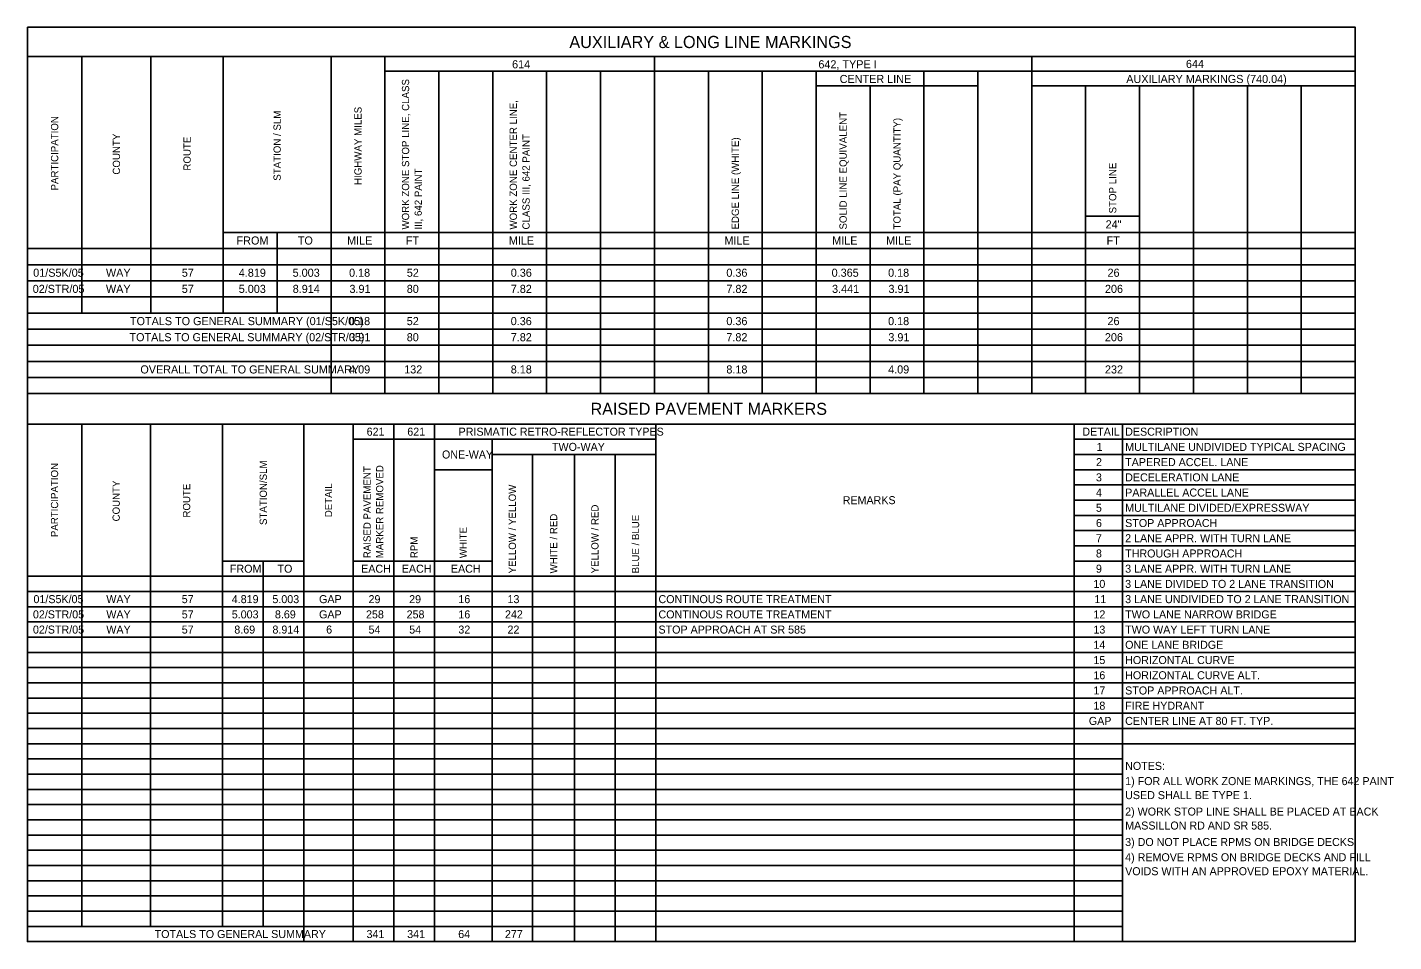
# Model space of a CAD drawing. Extents: x 169.3 to 200.7, y -37 to -16.
import ezdxf

# ---------------------------------------------------------------- set-up
doc = ezdxf.new("R2010")
doc.units = 0
doc.layers.add('SC_Scratch1', color=7, linetype='Continuous')
doc.layers.add('SH_Text', color=7, linetype='Continuous')

msp = doc.modelspace()

# ---------------------------------------------------------------- linework, layer by layer
at = {"layer": 'SC_Scratch1'}
msp.add_lwpolyline([(169.301, -15.985), (199.801, -15.985), (199.801, -36.985), (169.301, -36.985)], close=True, dxfattribs=at)
at = {"layer": 'SH_Text'}
for p, q in [((169.301, -15.985), (199.801, -15.985)), ((169.301, -15.985), (169.301, -24.398)), ((199.801, -15.985), (199.801, -24.398)), ((169.301, -16.658), (199.801, -16.658)), ((170.554, -16.658), (170.554, -22.547)), ((172.139, -16.658), (172.139, -22.547)), ((173.8, -16.658), (173.8, -22.547)), ((176.277, -16.658), (176.277, -24.398)), ((177.515, -16.658), (177.515, -24.398)), ((183.705, -16.658), (183.705, -24.398)), ((192.372, -16.658), (192.372, -24.398)), ((177.515, -16.995), (199.801, -16.995)), ((178.753, -16.995), (178.753, -24.398)), ((179.991, -16.995), (179.991, -24.398)), ((181.229, -16.995), (181.229, -24.398)), ((182.467, -16.995), (182.467, -24.398)), ((184.943, -16.995), (184.943, -24.398)), ((186.182, -16.995), (186.182, -24.398)), ((187.42, -16.995), (187.42, -24.398)), ((189.896, -16.995), (189.896, -24.398)), ((191.134, -16.995), (191.134, -24.398)), ((187.42, -17.331), (191.134, -17.331)), ((188.658, -17.331), (188.658, -24.398)), ((192.372, -17.331), (199.801, -17.331)), ((193.61, -17.331), (193.61, -24.398)), ((194.848, -17.331), (194.848, -24.398)), ((196.086, -17.331), (196.086, -24.398)), ((197.325, -17.331), (197.325, -24.398)), ((198.563, -17.331), (198.563, -24.398)), ((193.61, -20.326), (194.848, -20.326)), ((173.8, -20.696), (199.801, -20.696)), ((175.038, -20.696), (175.038, -22.547)), ((169.301, -21.066), (199.801, -21.066)), ((169.301, -21.437), (199.801, -21.437)), ((169.301, -21.807), (199.801, -21.807)), ((169.301, -22.177), (199.801, -22.177)), ((169.301, -22.547), (199.801, -22.547)), ((169.301, -22.917), (199.801, -22.917)), ((169.301, -23.287), (199.801, -23.287)), ((169.301, -23.658), (199.801, -23.658)), ((169.301, -24.028), (199.801, -24.028)), ((169.301, -24.398), (199.801, -24.398)), ((169.301, -24.398), (169.301, -36.985)), ((169.301, -24.398), (199.801, -24.398)), ((199.801, -24.398), (199.801, -36.985)), ((169.301, -25.097), (199.801, -25.097)), ((170.55, -25.097), (170.55, -36.635)), ((172.131, -25.097), (172.131, -36.635)), ((173.787, -25.097), (173.787, -36.635)), ((175.654, -25.097), (175.654, -36.985)), ((176.783, -25.097), (176.783, -36.985)), ((177.716, -25.097), (177.716, -36.985)), ((178.65, -25.097), (178.65, -36.985)), ((183.738, -25.097), (183.738, -36.985)), ((193.343, -25.097), (193.343, -36.985)), ((194.457, -25.097), (194.457, -36.985)), ((176.783, -25.447), (183.738, -25.447)), ((179.974, -25.447), (179.974, -36.985)), ((193.343, -25.447), (199.801, -25.447)), ((179.974, -25.796), (183.738, -25.796)), ((180.908, -25.796), (180.908, -36.985)), ((181.871, -25.796), (181.871, -36.985)), ((182.805, -25.796), (182.805, -36.985)), ((193.343, -25.796), (199.801, -25.796)), ((178.65, -26.146), (179.974, -26.146)), ((193.343, -26.146), (199.801, -26.146)), ((193.343, -26.496), (199.801, -26.496)), ((193.343, -26.845), (199.801, -26.845)), ((193.343, -27.195), (199.801, -27.195)), ((193.343, -27.545), (199.801, -27.545)), ((193.343, -27.894), (199.801, -27.894)), ((173.787, -28.244), (175.654, -28.244)), ((174.72, -28.244), (174.72, -36.635)), ((176.783, -28.244), (179.974, -28.244)), ((193.343, -28.244), (199.801, -28.244)), ((169.301, -28.594), (199.801, -28.594)), ((169.301, -28.943), (199.801, -28.943)), ((169.301, -29.293), (199.801, -29.293)), ((169.301, -29.643), (199.801, -29.643)), ((169.301, -29.992), (199.801, -29.992)), ((169.301, -30.342), (199.801, -30.342)), ((169.301, -30.691), (199.801, -30.691)), ((169.301, -31.041), (199.801, -31.041)), ((169.301, -31.391), (199.801, -31.391)), ((169.301, -31.74), (199.801, -31.74)), ((169.301, -32.09), (199.801, -32.09)), ((169.301, -32.44), (199.801, -32.44)), ((169.301, -32.789), (194.457, -32.789)), ((169.301, -33.139), (194.457, -33.139)), ((169.301, -33.489), (194.457, -33.489)), ((169.301, -33.838), (194.457, -33.838)), ((169.301, -34.188), (194.457, -34.188)), ((169.301, -34.538), (194.457, -34.538)), ((169.301, -34.887), (194.457, -34.887)), ((169.301, -35.237), (194.457, -35.237)), ((169.301, -35.587), (194.457, -35.587)), ((169.301, -35.936), (194.457, -35.936)), ((169.301, -36.286), (194.457, -36.286)), ((169.301, -36.635), (194.457, -36.635)), ((169.301, -36.985), (199.801, -36.985))]:
    msp.add_line(p, q, dxfattribs=at)

# ---------------------------------------------------------------- texts
for s, height, p in [('AUXILIARY & LONG LINE MARKINGS', 0.27863, (181.751, -16.461)), ('614', 0.1858, (180.436, -16.927)), ('642, TYPE I', 0.18575, (187.471, -16.927)), ('644', 0.1858, (195.913, -16.919)), ('CENTER LINE', 0.18575, (187.96, -17.264)), ('AUXILIARY MARKINGS (740.04)', 0.18575, (194.543, -17.264)), ('24"', 0.1858, (194.068, -20.604)), ('FROM', 0.1858, (174.107, -20.974)), ('TO', 0.1858, (175.514, -20.974)), ('MILE', 0.1858, (176.646, -20.974)), ('FT', 0.1858, (177.995, -20.974)), ('MILE', 0.1858, (180.361, -20.974)), ('MILE', 0.1858, (185.313, -20.974)), ('MILE', 0.1858, (187.789, -20.974)), ('MILE', 0.1858, (189.027, -20.974)), ('FT', 0.1858, (194.091, -20.974)), ('01/S5K/05', 0.1858, (169.436, -21.714)), ('WAY', 0.1858, (171.107, -21.714)), ('57', 0.1858, (172.849, -21.714)), ('4.819', 0.1858, (174.158, -21.714)), ('5.003', 0.1858, (175.395, -21.714)), ('0.18', 0.1858, (176.691, -21.714)), ('52', 0.1858, (178.017, -21.714)), ('0.36', 0.1858, (180.405, -21.714)), ('0.36', 0.1858, (185.357, -21.714)), ('0.365', 0.1858, (187.775, -21.714)), ('0.18', 0.1858, (189.072, -21.714)), ('26', 0.1858, (194.112, -21.714)), ('02/STR/05', 0.1858, (169.425, -22.085)), ('WAY', 0.1858, (171.107, -22.085)), ('57', 0.1858, (172.849, -22.085)), ('5.003', 0.1858, (174.157, -22.085)), ('8.914', 0.1858, (175.397, -22.085)), ('3.91', 0.1858, (176.7, -22.085)), ('80', 0.1858, (178.016, -22.085)), ('7.82', 0.1858, (180.405, -22.085)), ('7.82', 0.1858, (185.358, -22.085)), ('3.441', 0.1858, (187.785, -22.085)), ('3.91', 0.1858, (189.081, -22.085)), ('206', 0.1858, (194.053, -22.085)), ('TOTALS TO GENERAL SUMMARY (01/S5K/05)', 0.18575, (171.659, -22.825)), ('0.18', 0.1858, (176.691, -22.825)), ('52', 0.1858, (178.016, -22.825)), ('0.36', 0.1858, (180.404, -22.825)), ('0.36', 0.1858, (185.357, -22.825)), ('0.18', 0.1858, (189.072, -22.825)), ('26', 0.1858, (194.111, -22.825)), ('TOTALS TO GENERAL SUMMARY (02/STR/05)', 0.18575, (171.647, -23.195)), ('3.91', 0.1858, (176.697, -23.195)), ('80', 0.1858, (178.016, -23.195)), ('7.82', 0.1858, (180.405, -23.195)), ('7.82', 0.1858, (185.357, -23.195)), ('3.91', 0.1858, (189.078, -23.195)), ('206', 0.1858, (194.052, -23.195)), ('OVERALL TOTAL TO GENERAL SUMMARY', 0.18575, (171.897, -23.935)), ('4.09', 0.1858, (176.692, -23.935)), ('132', 0.1858, (177.957, -23.935)), ('8.18', 0.1858, (180.405, -23.935)), ('8.18', 0.1858, (185.357, -23.935)), ('4.09', 0.1858, (189.073, -23.935)), ('232', 0.1858, (194.053, -23.935)), ('RAISED PAVEMENT MARKERS', 0.27572, (182.239, -24.885)), ('621', 0.1838, (177.094, -25.364)), ('621', 0.1838, (178.028, -25.364)), ('PRISMATIC RETRO-REFLECTOR TYPES', 0.18381, (179.207, -25.364)), ('DETAIL', 0.1838, (193.533, -25.364)), ('DESCRIPTION', 0.18381, (194.517, -25.364)), ('ONE-WAY', 0.1838, (178.825, -25.888)), ('TWO-WAY', 0.1838, (181.352, -25.713)), ('1', 0.184, (193.861, -25.713)), ('MULTILANE UNDIVIDED TYPICAL SPACING', 0.18381, (194.517, -25.713)), ('2', 0.184, (193.847, -26.063)), ('TAPERED ACCEL. LANE', 0.18381, (194.517, -26.063)), ('3', 0.184, (193.846, -26.413)), ('DECELERATION LANE', 0.18381, (194.517, -26.413)), ('4', 0.184, (193.847, -26.762)), ('PARALLEL ACCEL LANE', 0.18381, (194.517, -26.762)), ('REMARKS', 0.1838, (188.029, -26.937)), ('5', 0.184, (193.846, -27.112)), ('MULTILANE DIVIDED/EXPRESSWAY', 0.18381, (194.517, -27.112)), ('6', 0.184, (193.846, -27.462)), ('STOP APPROACH', 0.18381, (194.517, -27.462)), ('7', 0.184, (193.846, -27.811)), ('2 LANE APPR. WITH TURN LANE', 0.18381, (194.517, -27.811)), ('8', 0.184, (193.846, -28.161)), ('THROUGH APPROACH', 0.18381, (194.517, -28.161)), ('FROM', 0.1838, (173.954, -28.511)), ('TO', 0.1838, (175.048, -28.511)), ('EACH', 0.1838, (176.968, -28.511)), ('EACH', 0.1838, (177.901, -28.511)), ('EACH', 0.1838, (179.03, -28.511)), ('9', 0.184, (193.846, -28.511)), ('3 LANE APPR. WITH TURN LANE', 0.18381, (194.517, -28.511)), ('10', 0.1838, (193.788, -28.86)), ('3 LANE DIVIDED TO 2 LANE TRANSITION', 0.18381, (194.517, -28.86)), ('01/S5K/05', 0.1838, (169.442, -29.21)), ('WAY', 0.1838, (171.115, -29.21)), ('57', 0.1838, (172.848, -29.21)), ('4.819', 0.1838, (173.997, -29.21)), ('5.003', 0.1838, (174.93, -29.21)), ('GAP', 0.1838, (176.002, -29.21)), ('29', 0.1838, (177.138, -29.21)), ('29', 0.1838, (178.071, -29.21)), ('16', 0.1838, (179.201, -29.21)), ('13', 0.1838, (180.33, -29.21)), ('CONTINOUS ROUTE TREATMENT', 0.18381, (183.798, -29.21)), ('11', 0.1838, (193.81, -29.21)), ('3 LANE UNDIVIDED TO 2 LANE TRANSITION', 0.18381, (194.517, -29.21)), ('02/STR/05', 0.1838, (169.43, -29.56)), ('WAY', 0.1838, (171.115, -29.56)), ('57', 0.1838, (172.848, -29.56)), ('5.003', 0.1838, (173.997, -29.56)), ('8.69', 0.1838, (174.988, -29.56)), ('GAP', 0.1838, (176.002, -29.56)), ('258', 0.1838, (177.08, -29.56)), ('258', 0.1838, (178.013, -29.56)), ('16', 0.1838, (179.201, -29.56)), ('242', 0.1838, (180.272, -29.56)), ('CONTINOUS ROUTE TREATMENT', 0.18381, (183.798, -29.56)), ('12', 0.1838, (193.789, -29.56)), ('TWO LANE NARROW BRIDGE', 0.18381, (194.517, -29.56)), ('02/STR/05', 0.1838, (169.43, -29.909)), ('WAY', 0.1838, (171.115, -29.909)), ('57', 0.1838, (172.848, -29.909)), ('8.69', 0.1838, (174.055, -29.909)), ('8.914', 0.1838, (174.931, -29.909)), ('6', 0.184, (176.165, -29.909)), ('54', 0.1838, (177.138, -29.909)), ('54', 0.1838, (178.072, -29.909)), ('32', 0.1838, (179.201, -29.909)), ('22', 0.1838, (180.33, -29.909)), ('STOP APPROACH AT SR 585', 0.18381, (183.798, -29.909)), ('13', 0.1838, (193.788, -29.909)), ('TWO WAY LEFT TURN LANE', 0.18381, (194.517, -29.909)), ('14', 0.1838, (193.788, -30.259)), ('ONE LANE BRIDGE', 0.18381, (194.517, -30.259)), ('15', 0.1838, (193.788, -30.609)), ('HORIZONTAL CURVE', 0.18381, (194.517, -30.609)), ('16', 0.1838, (193.788, -30.958)), ('HORIZONTAL CURVE ALT.', 0.18381, (194.517, -30.958)), ('17', 0.1838, (193.788, -31.308)), ('STOP APPROACH ALT.', 0.18381, (194.517, -31.308)), ('18', 0.1838, (193.788, -31.657)), ('FIRE HYDRANT', 0.18381, (194.517, -31.657)), ('GAP', 0.1838, (193.683, -32.007)), ('CENTER LINE AT 80 FT. TYP.', 0.18381, (194.517, -32.007)), ('NOTES:', 0.1838, (194.517, -33.04)), ('1) FOR ALL WORK ZONE MARKINGS, THE 642 PAINT ', 0.18381, (194.517, -33.389)), ('USED SHALL BE TYPE 1.', 0.18381, (194.517, -33.711)), ('2) WORK STOP LINE SHALL BE PLACED AT BACK ', 0.18381, (194.517, -34.089)), ('MASSILLON RD AND SR 585.', 0.18381, (194.517, -34.41)), ('3) DO NOT PLACE RPMS ON BRIDGE DECKS.', 0.18381, (194.517, -34.788)), ('4) REMOVE RPMS ON BRIDGE DECKS AND FILL ', 0.18381, (194.517, -35.138)), ('VOIDS WITH AN APPROVED EPOXY MATERIAL.', 0.18381, (194.517, -35.459)), ('TOTALS TO GENERAL SUMMARY', 0.18381, (172.225, -36.902)), ('341', 0.1838, (177.092, -36.902)), ('341', 0.1838, (178.026, -36.902)), ('64', 0.1838, (179.198, -36.902)), ('277', 0.1838, (180.271, -36.902))]:
    msp.add_text(s, height=height, dxfattribs=at).set_placement(p)
for s, height, p in [('WORK ZONE STOP LINE, CLASS ', 0.16669, (178.071, -20.629)), ('HIGHWAY MILES', 0.16669, (176.979, -19.606)), ('WORK ZONE CENTER LINE, ', 0.16669, (180.547, -20.629)), ('PARTICIPATION', 0.16669, (170.011, -19.733)), ('STATION / SLM', 0.16669, (175.122, -19.508)), ('SOLID LINE EQUIVALENT', 0.16669, (188.122, -20.629)), ('TOTAL (PAY QUANTITY)', 0.16669, (189.36, -20.629)), ('COUNTY', 0.1667, (171.43, -19.368)), ('ROUTE', 0.1667, (173.053, -19.276)), ('CLASS III, 642 PAINT', 0.16669, (180.839, -20.629)), ('EDGE LINE (WHITE)', 0.16669, (185.646, -20.629)), ('STOP LINE', 0.1667, (194.313, -20.259)), ('III, 642 PAINT', 0.16669, (178.363, -20.629)), ('PARTICIPATION', 0.1662, (170.009, -27.694)), ('STATION/SLM', 0.1662, (174.803, -27.415)), ('RAISED PAVEMENT ', 0.1662, (177.187, -28.177)), ('MARKER REMOVED', 0.1662, (177.478, -28.177)), ('COUNTY', 0.1662, (171.424, -27.333)), ('ROUTE', 0.1662, (173.042, -27.244)), ('DETAIL', 0.1662, (176.301, -27.237)), ('YELLOW / YELLOW', 0.1662, (180.524, -28.527)), ('YELLOW / RED', 0.1662, (182.421, -28.527)), ('WHITE / RED', 0.1662, (181.473, -28.527)), ('BLUE / BLUE', 0.1662, (183.354, -28.527)), ('WHITE', 0.1662, (179.395, -28.177)), ('RPM', 0.1662, (178.266, -28.177))]:
    msp.add_text(s, height=height, rotation=90, dxfattribs=at).set_placement(p)

doc.saveas('drawing.dxf')
